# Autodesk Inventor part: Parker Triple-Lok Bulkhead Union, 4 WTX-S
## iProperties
Shininess: 27.0
Category: Hydraulics
Created: 2001-03
Part Number: Parker Triple-Lok Bulkhead Union, 4 WTX-S
Document SubType Name: Modeling
Designer: QBZ
Material: Steel, Mild
Description: Parker Triple-Lok Bulkhead Union, 4 WTX-S
Catalog Web Link: http://www.aeroquip.com
Density: 0.0
Volumn: 0.0
Area: 0.0
PropertySet Name: Model Information
Control State: 0
Master: False
Checked Out: False
Last Check In Date: 2003-09-27
Last Check In By: Charles Bliss
Title: JIC Bulkhead Union
Author: QBZ
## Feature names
1. Revolution1
2. Long end [Hole]
3. Short End [Hole]
4. Revolution2
